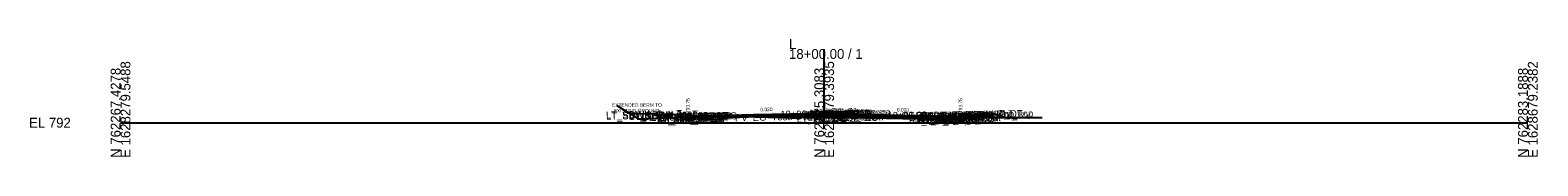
# Model space of a CAD drawing. Extents: x -26 to 4403, y -510 to 9556.
# Drawn here: x -25.7 to 402.8, y 7990.3 to 8023.7 of the extents above; entities that cross this region are included whole.
import ezdxf

# ---------------------------------------------------------------- set-up
doc = ezdxf.new("R2010")
doc.units = 0
for name, color, linetype in [('Default', 7, 'Continuous'), ('Exist CMT Pavement', 7, 'Continuous'), ('Exist Cross Section Cell', 7, 'Continuous'), ('Exist XS Ground Line', 7, 'Continuous'), ('Exist XS Void Line', 7, 'Continuous'), ('Prop CMT Conc Surface', 7, 'Continuous'), ('Prop CMT Concrete Structures', 7, 'Continuous'), ('Prop CMT Pvmt Course 1', 7, 'Continuous'), ('Prop CMT Pvmt Course 1 CG', 7, 'Continuous'), ('Prop CMT Pvmt Course 1 Wedge', 7, 'Continuous'), ('Prop CMT Pvmt Course 2', 7, 'Continuous'), ('Prop CMT Pvmt Course 2 Wedge', 7, 'Continuous'), ('Prop CMT Pvmt Course 3', 7, 'Continuous'), ('Prop CMT Pvmt Course 3 Wedge', 7, 'Continuous'), ('Prop CMT Pvmt Surface', 7, 'Continuous'), ('Prop CMT Pvmt Wedge Surface 1', 7, 'Continuous'), ('Prop CMT Pvmt Wedge Surface 2', 7, 'Continuous'), ('Prop CMT Pvmt Wedge Surface 3', 7, 'Continuous'), ('Prop CMT Slope Grass', 7, 'Continuous'), ('Prop CMT Subgrade Earthwork', 7, 'Continuous'), ('Prop XS Hydro Elevations', 7, 'Continuous'), ('Prop XS SE Text', 7, 'Continuous'), ('Prop XS Side Slope Text', 7, 'Continuous'), ('Scratch_Level_0', 7, 'Continuous')]:
    doc.layers.add(name, color=color, linetype=linetype)

msp = doc.modelspace()

# ---------------------------------------------------------------- linework, layer by layer
at = {"layer": 'Exist CMT Pavement'}
msp.add_lwpolyline([(163.26, 8001.75), (170.45, 8001.85), (170.87, 8001.85), (180.42, 8001.71), (180.96, 8001.69), (190, 8001.39)], dxfattribs=at)
at = {"layer": 'Exist Cross Section Cell'}
for p, q in [((200, 8000), (200, 8020.95)), ((0, 8000), (200, 8000)), ((200, 8000), (400, 8000))]:
    msp.add_line(p, q, dxfattribs=at)
at = {"layer": 'Exist XS Ground Line'}
for p, q in [((141.05, 8004.9), (147.24, 8001.1)), ((147.24, 8001.1), (149.85, 8001.1))]:
    msp.add_line(p, q, dxfattribs=at)
msp.add_lwpolyline([(149.85, 8001.1), (160.72, 8001.72), (170.45, 8001.85), (170.87, 8001.85), (180.42, 8001.71), (180.96, 8001.69), (190.58, 8001.37), (191.25, 8001.35), (192.95, 8001.18), (193.72, 8001.62), (196.22, 8001.45)], dxfattribs=at)
at = {"layer": 'Exist XS Void Line'}
msp.add_line((196.22, 8001.45), (261.91, 8001.45), dxfattribs=at)
at = {"layer": 'Prop CMT Conc Surface'}
for points in [[(156.75, 8002.33), (151.75, 8002.44)], [(161.25, 8001.75), (161.25, 8002.24), (160.75, 8002.24)], [(163.25, 8001.87), (161.25, 8001.75)], [(236.75, 8001.87), (238.75, 8001.75)], [(238.75, 8001.75), (238.75, 8002.24), (239.25, 8002.24)], [(243.25, 8002.33), (248.25, 8002.44)]]:
    msp.add_lwpolyline(points, dxfattribs=at)
at = {"layer": 'Prop CMT Concrete Structures'}
for points in [[(151.75, 8002.1), (151.75, 8002.44)], [(151.75, 8002.44), (156.75, 8002.33)], [(156.75, 8002), (151.75, 8002.1)], [(156.75, 8002.33), (156.75, 8002)], [(163.25, 8001.87), (161.25, 8001.75), (161.25, 8002.24), (160.75, 8002.24)], [(160.75, 8002.24), (160.75, 8001.23), (163.25, 8001.28)], [(163.25, 8001.28), (163.25, 8001.87)], [(208, 8002.44), (207.99, 8002.61), (207.24, 8002.86), (206, 8003.12), (204.76, 8003.1), (204.01, 8002.85), (204, 8002.68)], [(204, 8002.68), (208, 8002.44)], [(236.75, 8001.87), (238.75, 8001.75), (238.75, 8002.24), (239.25, 8002.24)], [(239.25, 8002.24), (239.25, 8001.23), (236.75, 8001.28)], [(236.75, 8001.28), (236.75, 8001.87)], [(248.25, 8002.44), (243.25, 8002.33)], [(243.25, 8002.33), (243.25, 8002)], [(243.25, 8002), (248.25, 8002.1)], [(248.25, 8002.1), (248.25, 8002.44)]]:
    msp.add_lwpolyline(points, dxfattribs=at)
at = {"layer": 'Prop CMT Pvmt Course 1'}
for points in [[(204, 8002.68), (163.25, 8001.87)], [(163.25, 8001.74), (204, 8002.55)], [(163.25, 8001.87), (163.25, 8001.62), (163.25, 8001.62), (163.25, 8001.74)], [(204, 8002.68), (208, 8002.44)], [(204, 8002.43), (204, 8002.68)], [(204, 8002.43), (204, 8002.68)], [(204, 8002.55), (204, 8002.43), (204, 8002.43)], [(208, 8002.19), (204, 8002.43)], [(208, 8002.44), (208, 8002.19)], [(208, 8002.44), (236.75, 8001.87)], [(208, 8002.19), (208, 8002.44)], [(236.75, 8001.62), (208, 8002.19)], [(236.75, 8001.87), (236.75, 8001.62)]]:
    msp.add_lwpolyline(points, dxfattribs=at)
msp.add_lwpolyline([(208, 8002.19), (208, 8002.31), (208, 8002.31), (208, 8002.19)], close=True, dxfattribs=at)
at = {"layer": 'Prop CMT Pvmt Course 1 CG'}
for points in [[(163.25, 8001.28), (160.25, 8001.22), (159.91, 8000.88)], [(159.91, 8000.88), (163.25, 8000.95)], [(236.75, 8001.28), (239.75, 8001.22), (240.09, 8000.88)], [(236.75, 8000.95), (236.75, 8001.28)], [(240.09, 8000.88), (236.75, 8000.95)]]:
    msp.add_lwpolyline(points, dxfattribs=at)
at = {"layer": 'Prop CMT Pvmt Course 1 Wedge'}
for points in [[(204, 8002.43), (196.22, 8002.27), (193.79, 8002.23), (193.72, 8002.22), (193, 8002.21), (192.99, 8002.21), (192.95, 8002.21), (191.55, 8002.18), (191.25, 8002.18), (190.58, 8002.16), (180.96, 8001.97), (180.42, 8001.96), (173.28, 8001.82), (170.87, 8001.85), (170.45, 8001.85), (164.78, 8001.77)], [(164.78, 8001.77), (170.45, 8001.88)], [(170.45, 8001.88), (170.87, 8001.89), (180.42, 8002.08), (180.96, 8002.09), (190.58, 8002.29), (191.25, 8002.3), (191.55, 8002.31), (192.95, 8002.33), (192.99, 8002.33), (193, 8002.33), (193.72, 8002.35), (193.79, 8002.35), (196.22, 8002.4), (204, 8002.55)], [(204, 8002.55), (204, 8002.43)]]:
    msp.add_lwpolyline(points, dxfattribs=at)
at = {"layer": 'Prop CMT Pvmt Course 2'}
for points in [[(163.25, 8001.28), (163.25, 8001.28), (163.25, 8001.62), (163.25, 8001.62)], [(163.25, 8001.62), (163.25, 8001.28)], [(204, 8002.43), (208, 8002.19)], [(204, 8002.1), (204, 8002.43)], [(208, 8001.86), (204, 8002.1)], [(208, 8002.19), (208, 8001.86)], [(208, 8001.86), (208, 8002.19)], [(208, 8002.19), (236.75, 8001.62)], [(236.75, 8001.28), (208, 8001.86)], [(236.75, 8001.62), (236.75, 8001.28)]]:
    msp.add_lwpolyline(points, dxfattribs=at)
at = {"layer": 'Prop CMT Pvmt Course 2 Wedge'}
for points in [[(204, 8002.1), (196.22, 8001.94), (193.79, 8001.89), (193.72, 8001.89), (193, 8001.88), (192.99, 8001.88), (192.95, 8001.88), (191.55, 8001.85), (191.25, 8001.84), (190.58, 8001.83), (182.06, 8001.66), (180.96, 8001.69), (180.42, 8001.71), (173.28, 8001.82)], [(173.28, 8001.82), (180.42, 8001.96)], [(180.42, 8001.96), (180.96, 8001.97), (190.58, 8002.16), (191.25, 8002.18), (191.55, 8002.18), (192.95, 8002.21), (192.99, 8002.21), (193, 8002.21), (193.72, 8002.22), (193.79, 8002.23), (196.22, 8002.27), (204, 8002.43)], [(204, 8002.43), (204, 8002.1)]]:
    msp.add_lwpolyline(points, dxfattribs=at)
at = {"layer": 'Prop CMT Pvmt Course 3'}
for points in [[(163.25, 8001.28), (163.25, 8001.28), (163.25, 8000.95), (163.25, 8000.95)], [(163.25, 8000.95), (163.25, 8001.28)], [(204, 8002.1), (208, 8001.86)], [(204, 8001.76), (204, 8002.1)], [(208, 8001.52), (204, 8001.76)], [(208, 8001.86), (208, 8001.52)], [(208, 8001.86), (236.75, 8001.28)], [(208, 8001.52), (208, 8001.86)], [(236.75, 8000.95), (208, 8001.52)], [(236.75, 8001.28), (236.75, 8000.95)]]:
    msp.add_lwpolyline(points, dxfattribs=at)
at = {"layer": 'Prop CMT Pvmt Course 3 Wedge'}
for points in [[(182.05, 8001.66), (190.58, 8001.83)], [(204, 8001.45), (196.22, 8001.45), (193.79, 8001.62), (193.72, 8001.62), (193, 8001.2), (192.99, 8001.19), (192.95, 8001.18), (191.55, 8001.32), (191.25, 8001.35), (190.58, 8001.37), (182.05, 8001.66)], [(190.58, 8001.83), (191.25, 8001.84), (191.55, 8001.85), (192.95, 8001.88), (192.99, 8001.88), (193, 8001.88), (193.72, 8001.89), (193.79, 8001.89), (196.22, 8001.94), (204, 8002.1)]]:
    msp.add_lwpolyline(points, dxfattribs=at)
at = {"layer": 'Prop CMT Pvmt Surface'}
for points in [[(204, 8002.68), (163.25, 8001.87)], [(204, 8002.68), (208, 8002.44)], [(208, 8002.44), (236.75, 8001.87)]]:
    msp.add_lwpolyline(points, dxfattribs=at)
at = {"layer": 'Prop CMT Pvmt Wedge Surface 1'}
for points in [[(204, 8002.55), (163.25, 8001.74)], [(163.25, 8001.62), (163.25, 8001.87)], [(163.25, 8001.74), (163.25, 8001.62), (163.25, 8001.62)], [(204, 8002.68), (204, 8002.43), (204, 8002.43), (204, 8002.55)]]:
    msp.add_lwpolyline(points, dxfattribs=at)
at = {"layer": 'Prop CMT Pvmt Wedge Surface 2'}
for points in [[(204, 8002.43), (163.25, 8001.62)], [(163.25, 8001.62), (163.25, 8001.87)], [(204, 8002.68), (204, 8002.43)]]:
    msp.add_lwpolyline(points, dxfattribs=at)
at = {"layer": 'Prop CMT Pvmt Wedge Surface 3'}
for points in [[(204, 8002.1), (163.25, 8001.28)], [(163.25, 8001.28), (163.25, 8001.87)], [(204, 8002.68), (204, 8002.1)]]:
    msp.add_lwpolyline(points, dxfattribs=at)
at = {"layer": 'Prop CMT Slope Grass'}
for points in [[(151.25, 8002.44), (144.85, 8002.56)], [(160.75, 8002.24), (151.25, 8002.44)], [(239.25, 8002.24), (248.25, 8002.43)], [(248.25, 8002.43), (248.74, 8002.43), (251.64, 8001.47)]]:
    msp.add_lwpolyline(points, dxfattribs=at)
at = {"layer": 'Prop CMT Subgrade Earthwork'}
msp.add_line((190, 8001.39), (190, 8001.48), dxfattribs=at)
for points in [[(163.25, 8000.95), (159.91, 8000.88), (158.5, 8002.29)], [(163.25, 8000.95), (163.26, 8001.75)], [(163.25, 8000.95), (163.25, 8000.95)], [(204, 8001.76), (190, 8001.48)], [(204, 8001.76), (208, 8001.52)], [(208, 8001.52), (236.75, 8000.95)], [(236.75, 8000.95), (240.09, 8000.88), (241.5, 8002.29)]]:
    msp.add_lwpolyline(points, dxfattribs=at)

# ---------------------------------------------------------------- texts
at = {"layer": 'Default'}
msp.add_text('-', height=0.0001, dxfattribs=at).set_placement((0, 8000))
at = {"layer": 'Exist Cross Section Cell'}
for s, p in [('L', (190, 8020.95)), ('18+00.00 / 1', (190, 8018.15)), ('EL 792', (-26, 7998.6))]:
    msp.add_text(s, height=2.8, dxfattribs=at).set_placement(p)
for s, p in [('N 762267.4278', (0, 7990)), ('E 1628279.5488', (2.8, 7990)), ('N 762275.3083', (200, 7990)), ('E 1628479.3935', (202.8, 7990)), ('N 762283.1888', (400, 7990)), ('E 1628679.2382', (402.8, 7990))]:
    msp.add_text(s, height=2.8, rotation=90, dxfattribs=at).set_placement(p)
at = {"layer": 'Prop XS Hydro Elevations'}
for p in [(161.75, 8002.75), (239.25, 8002.75)]:
    msp.add_text('793.75', height=1, rotation=90, dxfattribs=at).set_placement(p)
at = {"layer": 'Prop XS SE Text'}
for rotation, p in [(1.1458, (181.86, 8003.24)), (358.8543, (220.65, 8003.19))]:
    msp.add_text('0.020', height=1, rotation=rotation, dxfattribs=at).set_placement(p)
at = {"layer": 'Prop XS Side Slope Text'}
for s, p in [('EXTENDED BERM TO', (139.68, 8004.54)), ('EXISTING GROUND', (140.19, 8002.91))]:
    msp.add_text(s, height=1, dxfattribs=at).set_placement(p)
msp.add_text('3:1', height=1, rotation=341.5651, dxfattribs=at).set_placement((249.56, 8002.81))
at = {"layer": 'Scratch_Level_0'}
for s, p in [('LT_SDWK_Out_Top', (138.01, 8001.16)), ('LT_SDWK_Out_Bot', (138.04, 8000.83)), ('LT_SDWK_In_Top', (144.63, 8001.09)), ('LT_SDWK_In_Bot', (144.66, 8000.76)), ('LT_PV_Sub_Tie_Out', (148.23, 8000.45)), ('LT_PV_OEEOP_EG', (150.82, 8000.5)), ('LT_Sub_OEEOP', (152.48, 7999.73)), ('LT_PV2_OEEOP', (152.58, 8000.4)), ('LT_PV3_OEEOP', (152.58, 8000.07)), ('LT_PV1_OEEOP', (153.15, 8000.54)), ('LT_Sub_OEOT', (153.35, 7999.75)), ('LT_PV2_OEOT', (153.45, 8000.42)), ('LT_PV3_OEOT', (153.45, 8000.09)), ('LT_PV1_OEOT', (154.01, 8000.68)), ('LT_PV_EG_TestPt', (170.06, 8000.33)), ('18+00.00', (187.56, 8001.35)), ('LT_PV_IEEOP_EG', (192.21, 8000.09)), ('LT_PV2_IEEOP', (193.97, 8001.23)), ('LT_PV3_IEEOP', (193.97, 8000.9)), ('LT_PV1_IEEOP', (194.54, 8001.37)), ('LT_PV2_PGL1', (194.9, 8001.25)), ('LT_PV3_PGL1', (194.9, 8000.91)), ('LT_PV2_PGL', (195.23, 8001.25)), ('LT_PV3_PGL', (195.23, 8000.92)), ('LT_PV4_PGL', (195.23, 8000.59)), ('LT_PV1_PGL', (195.8, 8001.52)), ('MI_Face In', (195.92, 8001.69)), ('RT_Sub_OEEOP', (197.19, 8000.31)), ('RT_PV2_OEEOP', (197.28, 8000.98)), ('RT_PV3_OEEOP', (197.28, 8000.64)), ('MI_Top In', (197.63, 8001.95)), ('18+00.00', (197.76, 8001.59)), ('RT_PV1_OEEOP', (197.85, 8001.11)), ('RT_PV2_IEEOP', (197.93, 8000.99)), ('MI_Face Out', (198.28, 8001.41)), ('18+00.00', (198.3, 8001.9)), ('MI_Top Out', (198.49, 8001.68)), ('RT_PV1_IEEOP', (198.49, 8001.12)), ('RT_PV2_PGL1', (198.86, 8001.01)), ('RT_PV3_PGL1', (198.86, 8000.67)), ('MI_Crown', (199.09, 8001.98)), ('RT_PV2_PGL', (199.19, 8001.01)), ('RT_PV4_PGL', (199.19, 8000.35)), ('MI_Bot Out', (199.28, 8001.27)), ('RT_PV1_PGL', (199.75, 8001.27)), ('18+00.00', (201.56, 8001.54)), ('18+00.00', (201.75, 8001.45)), ('18+00.00', (218.01, 8000.99)), ('RT_Sub_Trench_Out_DLT', (222.04, 8000.9)), ('RT_Sub_OEOT_CG', (224.1, 7999.69)), ('RT_CG_Top_Face', (225.99, 8000.99)), ('RT_CG1_Shelf_Out', (226.28, 7999.95)), ('RT_CG_Bot_IE', (226.64, 8000.08)), ('RT_Sub_OEOT', (226.8, 7999.75)), ('RT_PV2_OEOT', (226.9, 8000.42)), ('RT_PV3_OEOT', (226.9, 8000.08)), ('RT_CG_Top_Gut', (226.96, 8000.51)), ('RT_PV1_OEOT', (227.46, 8000.68)), ('RT_CG_Top_BOC', (227.51, 8001.01)), ('RT_CG_Bot_BOC', (227.54, 8000)), ('RT_Sub_OEOP', (230.17, 7999.68)), ('RT_SDWK_In_Top', (231.08, 8001.09)), ('RT_SDWK_In_Bot', (231.12, 8000.76)), ('18+00.00', (232.84, 8001.12)), ('18+00.00', (233.37, 8001.13)), ('RT_SDWK_Out_Top', (234.46, 8001.16)), ('RT_SDWK_Out_Bot', (234.49, 8000.83)), ('RT_Shld_O', (240.81, 8001.28))]:
    msp.add_text(s, height=2, rotation=1.1458, dxfattribs=at).set_placement(p)

doc.saveas('drawing.dxf')
